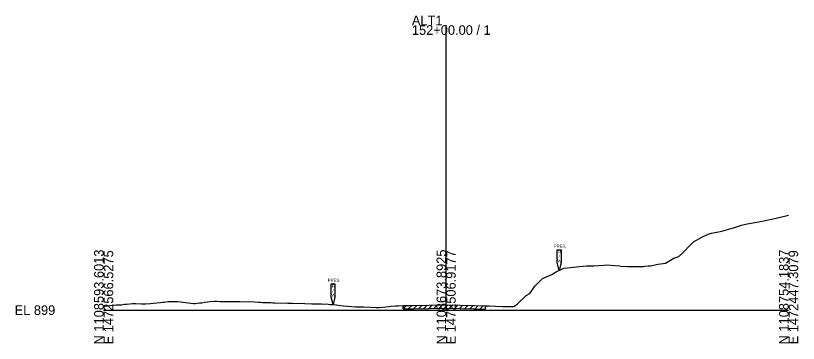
# Model space of a CAD drawing. Extents: x -26 to 2203, y -10 to 19568.
# Drawn here: x -25.7 to 202.8, y 13990.3 to 14086 of the extents above; entities that cross this region are included whole.
import ezdxf

# ---------------------------------------------------------------- set-up
doc = ezdxf.new("R2010")
doc.units = 0
for name, color, linetype in [('RD_GPK_XS_Cell', 7, 'Continuous'), ('RD_XS_ExGround', 7, 'Continuous'), ('RD_XS_ExPaveRet', 7, 'Continuous'), ('RD_XS_ExRW', 7, 'Continuous')]:
    doc.layers.add(name, color=color, linetype=linetype)

msp = doc.modelspace()

# ---------------------------------------------------------------- linework, layer by layer
at = {"layer": 'RD_GPK_XS_Cell'}
for p, q in [((100, 14000), (100, 14083.17)), ((0, 14000), (100, 14000)), ((100, 14000), (200, 14000))]:
    msp.add_line(p, q, dxfattribs=at)
at = {"layer": 'RD_XS_ExGround'}
msp.add_lwpolyline([(0, 14001.22), (1.1, 14001.27), (1.81, 14001.34), (3.64, 14001.56), (5.18, 14001.55), (6.06, 14001.74), (6.8, 14001.79), (8.46, 14001.93), (8.97, 14001.94), (9.28, 14001.93), (11.08, 14001.88), (11.85, 14001.87), (12.36, 14001.88), (13.65, 14001.94), (14.58, 14002), (15.5, 14002.09), (16.64, 14002.23), (17.2, 14002.3), (17.69, 14002.33), (18.8, 14002.49), (19.31, 14002.49), (21.07, 14002.53), (21.66, 14002.5), (23.87, 14002.26), (24.81, 14002.12), (25.41, 14002.08), (26.22, 14001.93), (26.73, 14001.9), (28, 14002.12), (28.65, 14002.17), (29.54, 14002.3), (31.11, 14002.48), (32.39, 14002.6), (33.03, 14002.6), (34, 14002.57), (35.18, 14002.55), (36.31, 14002.48), (39.28, 14002.49), (39.78, 14002.49), (41.21, 14002.47), (42.72, 14002.49), (45.24, 14002.32), (45.8, 14002.31), (46.43, 14002.27), (47.54, 14002.23), (48.07, 14002.2), (48.84, 14002.19), (49.4, 14002.14), (49.88, 14002.12), (53.76, 14002.07), (55.13, 14002.03), (58.73, 14001.96), (60.76, 14001.89), (61.79, 14001.81), (62.79, 14001.82), (63.62, 14001.81), (64.42, 14001.79), (64.99, 14001.8), (66.14, 14001.69), (66.7, 14001.67), (67.92, 14001.51), (69.19, 14001.34), (70.08, 14001.29), (73.57, 14000.95), (75.85, 14000.93), (77.86, 14000.86), (79.58, 14000.76), (80.57, 14000.8), (83.32, 14001.08), (83.94, 14001.16), (85.17, 14001.22), (86.02, 14001.28), (87.45, 14001.32), (90.29, 14001.37), (99.53, 14001.57), (100, 14001.56), (108.29, 14001.37), (111.36, 14001.3), (112.59, 14001.28), (114.43, 14001.17), (116.41, 14001.1), (118.99, 14001.07), (119.73, 14001.07), (120.84, 14001.8), (123.34, 14004.23), (124.42, 14004.85), (125.86, 14006.98), (128.16, 14009.27), (130.9, 14010.44), (131.89, 14011.08), (134.33, 14012.26), (136.28, 14012.48), (138.96, 14012.75), (140.05, 14012.86), (140.96, 14012.92), (143.1, 14012.92), (146, 14013.15), (146.84, 14013.18), (149.27, 14013), (150.58, 14012.92), (151.03, 14012.86), (152.91, 14012.74), (156.22, 14012.74), (157.61, 14012.77), (158.03, 14012.82), (158.95, 14012.9), (159.68, 14012.98), (161.91, 14013.43), (164.04, 14013.73), (166.51, 14015.13), (167.92, 14015.64), (169.26, 14016.92), (171.16, 14018.86), (172.21, 14019.93), (174.69, 14021.31), (176.53, 14022.18), (177.51, 14022.43), (180.47, 14023.09), (181.22, 14023.28), (184.2, 14024.15), (186.26, 14024.76), (187.94, 14025.24), (191.29, 14025.82), (191.68, 14025.89), (192.79, 14026.11), (195.41, 14026.64), (196.32, 14026.88), (199.15, 14027.55), (200, 14027.72)], dxfattribs=at)
at = {"layer": 'RD_XS_ExPaveRet'}
for p, q in [((87.45, 14000.34), (88.44, 14001.34)), ((87.45, 14000.34), (87.45, 14001.32)), ((87.45, 14001.32), (87.45, 14000.32)), ((87.45, 14000.34), (90.52, 14000.4)), ((87.45, 14000.32), (90.29, 14000.37)), ((88.95, 14000.37), (89.94, 14001.36)), ((90.29, 14000.37), (99.53, 14000.57)), ((90.45, 14000.37), (91.47, 14001.4)), ((90.52, 14000.4), (99.53, 14000.59)), ((91.95, 14000.41), (92.97, 14001.43)), ((93.45, 14000.44), (94.47, 14001.46)), ((94.95, 14000.47), (95.97, 14001.49)), ((96.45, 14000.5), (97.47, 14001.53)), ((97.95, 14000.54), (98.97, 14001.56)), ((99.45, 14000.57), (100.43, 14001.55)), ((99.53, 14000.57), (100, 14000.56)), ((100, 14000.58), (108.08, 14000.4)), ((100, 14000.56), (108.29, 14000.37)), ((100.95, 14000.54), (101.92, 14001.52)), ((102.45, 14000.5), (103.42, 14001.48)), ((103.95, 14000.47), (104.92, 14001.45)), ((105.45, 14000.44), (106.42, 14001.41)), ((106.95, 14000.4), (107.92, 14001.38)), ((108.08, 14000.4), (111.36, 14000.32)), ((108.29, 14000.37), (111.36, 14000.3)), ((108.45, 14000.39), (109.4, 14001.34)), ((109.95, 14000.35), (110.9, 14001.31)), ((111.36, 14001.32), (111.36, 14000.32)), ((111.36, 14001.3), (111.36, 14000.3))]:
    msp.add_line(p, q, dxfattribs=at)
at = {"layer": 'RD_XS_ExRW'}
for points in [[(132.45, 14017.63), (133.55, 14017.63), (133.55, 14013.8), (133, 14011.61), (132.45, 14013.8)], [(66.45, 14007.64), (67.55, 14007.64), (67.55, 14003.81), (67, 14001.62), (66.45, 14003.81)]]:
    msp.add_lwpolyline(points, close=True, dxfattribs=at)

# ---------------------------------------------------------------- texts
at = {"layer": 'RD_GPK_XS_Cell'}
for s, p in [('ALT1', (90, 14083.17)), ('152+00.00 / 1', (90, 14080.37)), ('EL 899', (-26, 13998.6))]:
    msp.add_text(s, height=2.8, dxfattribs=at).set_placement(p)
for s, p in [('N 1108593.6013', (0, 13990)), ('E 1472566.5275', (2.8, 13990)), ('N 1108673.8925', (100, 13990)), ('E 1472506.9177', (102.8, 13990)), ('N 1108754.1837', (200, 13990)), ('E 1472447.3079', (202.8, 13990))]:
    msp.add_text(s, height=2.8, rotation=90, dxfattribs=at).set_placement(p)
at = {"layer": 'RD_XS_ExRW'}
for s, p in [('PRES.', (131.45, 14018.26)), ('R', (132.71, 14016.54)), ('/', (132.83, 14015.23)), ('W', (132.53, 14013.91)), ('PRES.', (65.45, 14008.27)), ('R', (66.71, 14006.55)), ('W', (66.53, 14003.92)), ('/', (66.83, 14005.24))]:
    msp.add_text(s, height=0.875, dxfattribs=at).set_placement(p)

doc.saveas('drawing.dxf')
